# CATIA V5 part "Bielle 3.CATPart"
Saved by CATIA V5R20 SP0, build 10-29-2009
Part number: Bielle 3
Publications: "Arête", "Arête1", "Arête2", "Arête3", "Arête4", "Arête5", "Arête6", "Arête7", "Arête8", "Arête9", "Arête10", "Face", "Face1", "Face2", "Face3", "Face4", "Face5", "Face6"
Bounding box of the stored display mesh (mm): x -10 to 10, y 108.776 to 161.454, z 108.335 to 260.345
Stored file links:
  C:\Users\thinkmotion1\Desktop\Khaled_IAO_Pack2\IAO_2010_1412_jclement\Non_Optimise\Bielle 3.CATPart
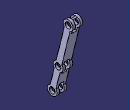
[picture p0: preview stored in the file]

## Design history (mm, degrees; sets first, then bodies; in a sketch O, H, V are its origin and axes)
Body1 (main body)
  Sketch1 on yz-plane, origin (0, 0, 0), H (0, 1, 0), V (0, 0, 1)
    line L1 (114.8735, 127.5388) -> (123.0432, 160.5427)
    line L2 (126.8877, 176.074) -> (143.7074, 244.0232)
    point P3 (126.8877, 176.074)
    line L3 (126.522, 124.6554) -> (134.6916, 157.6593)
    line L4 (138.5361, 173.1906) -> (155.3559, 241.1398)
    point P7 (138.5361, 173.1906)
    point P9 (130.7896, 166.8666)
    arc A1 centre (130.7896, 166.8666) radius 10 from (138.5361, 173.1906) to (134.6916, 157.6593) cw
    point P11 (138.5361, 173.1906)
    arc A2 centre (151.4539, 250.3471) radius 10 from (155.3559, 241.1398) to (143.7074, 244.0232) ccw
    point P12 (151.4539, 250.3471)
    arc A3 centre (118.7755, 118.3315) radius 10 from (114.8735, 127.5388) to (126.522, 124.6554) ccw
    point P13 (118.7755, 118.3315)
    construction line L5 (163.0325, 297.1226) -> (111.9425, 90.7272)
    circle A4 centre (151.4539, 250.3471) radius 6
    circle A5 centre (130.7896, 166.8666) radius 6
    point P16 (136.6138, 165.4249)
    circle A6 centre (118.7755, 118.3315) radius 6
    arc A7 centre (130.7896, 166.8666) radius 10 from (123.0432, 160.5427) to (126.8877, 176.074) cw
    radius A2 = 10
    distance L4 L2 = 12
    radius A1 = 10
    radius A3 = 10
    length L4 = 70
    length L3 = 34
    length L2 = 70
    length L1 = 34
    coincidence: P3 L1, P7 L3, P11 L4, L5 P13, P9 L5, P12 L5, A5 P16, P16 L3, P7 P11
    parallelism: L2 L1, L3 L2, L4 L3
    symmetry: L4 L2 L5
    tangency: A4 L4, A5 L4, A6 L3
  Pad1: profile Sketch1, direction (1, 0, 0), length 10, mirrored extent
  Sketch2 on face of Pad1 from Sketch1.L4, origin (0, 90.1421, -22.3133), H (-1, 0, 0), V (0, 0.2403, 0.9707)
    line L1 (-5, 289.2505) -> (5, 289.2505)
    line L2 (5, 289.2505) -> (5, 264.2505)
    line L3 (5, 264.2505) -> (-5, 264.2505)
    line L4 (-5, 264.2505) -> (-5, 289.2505)
    point P5 (-5, 205.4044)
    line L5 (-5, 205.4044) -> (5, 205.4044)
    line L6 (5, 205.4044) -> (5, 180.4044)
    line L7 (5, 180.4044) -> (-5, 180.4044)
    line L8 (-5, 180.4044) -> (-5, 205.4044)
    point P7 (5, 180.4044)
    point P9 (-5, 158.6101)
    line L9 (-5, 158.6101) -> (5, 158.6101)
    line L10 (5, 158.6101) -> (5, 133.6101)
    line L11 (5, 133.6101) -> (-5, 133.6101)
    line L12 (-5, 133.6101) -> (-5, 158.6101)
    point P11 (5, 133.6101)
    reference intersected line E1 through (0, 0) direction (0, -1) from yz-plane
    reference projected line E2 (10, 185.4044) -> (-10, 185.4044) from edge [face of Pad1 from Sketch1.A1 | face of Pad1 from Sketch1.L3]
    length L2 = 25
    length L1 = 10
    length L10 = 25
    length L6 = 25
    distance L7 E2 = 5
    horizontal: L1 H, L3 H, L5 H, L7 H, L9 H, L11 H
    vertical: L2 V, L4 V, L6 V, L8 V, L10 V, L12 V
    coincidence: P5 L4, P7 L2, P9 L4, P11 L2
    symmetry: L2 L4 E1
  Pocket1: profile Sketch2, direction (0, -0.9707, 0.2403), length 20, mirrored extent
